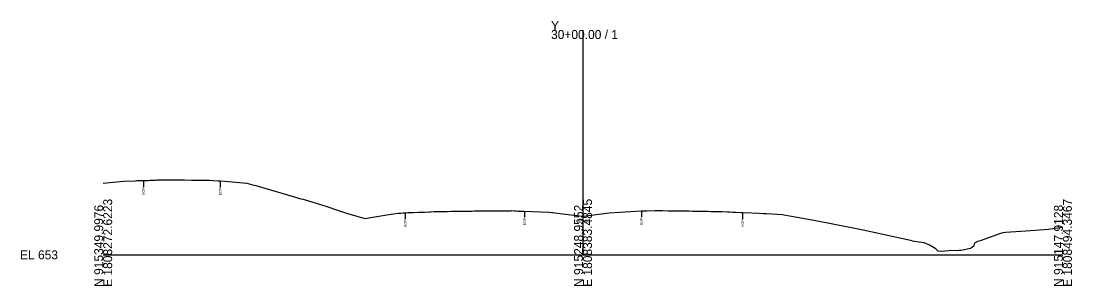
# Model space of a CAD drawing. Extents: x -26 to 3303, y -30 to 9580.
# Drawn here: x 1974.3 to 2302.8, y -9.7 to 72.9 of the extents above; entities that cross this region are included whole.
import ezdxf

# ---------------------------------------------------------------- set-up
doc = ezdxf.new("R2010")
doc.units = 0
for name, color, linetype in [('Exist Cross Section Cell', 7, 'Continuous'), ('Exist XS Center Line Elevation Label', 7, 'Continuous'), ('Exist XS Ground Line', 7, 'Continuous'), ('Old_Level_10', 7, 'Continuous')]:
    doc.layers.add(name, color=color, linetype=linetype)

msp = doc.modelspace()

# ---------------------------------------------------------------- linework, layer by layer
at = {"layer": 'Exist Cross Section Cell'}
for p, q in [((2150, 0), (2150, 70.15)), ((2000, 0), (2150, 0)), ((2150, 0), (2300, 0))]:
    msp.add_line(p, q, dxfattribs=at)
at = {"layer": 'Exist XS Ground Line'}
msp.add_lwpolyline([(2000, 22.36), (2005.33, 22.94), (2006.35, 23), (2009.84, 23.13), (2010.52, 23.16), (2011.55, 23.18), (2012.56, 23.21), (2013.38, 23.23), (2014.11, 23.25), (2014.72, 23.28), (2016.43, 23.35), (2016.86, 23.38), (2017.19, 23.38), (2017.49, 23.38), (2019.06, 23.38), (2020.95, 23.38), (2024.47, 23.37), (2025.36, 23.37), (2027.62, 23.35), (2028.24, 23.35), (2031.01, 23.33), (2031.46, 23.33), (2032.02, 23.33), (2033.16, 23.32), (2034.32, 23.2), (2035.97, 23.08), (2036.57, 23.05), (2038.02, 22.95), (2039.21, 22.86), (2044.91, 22.4), (2047.08, 21.79), (2047.69, 21.61), (2050.57, 20.77), (2059.38, 18.16), (2061.81, 17.49), (2062.49, 17.38), (2066.9, 16.03), (2068.93, 15.39), (2074.22, 13.61), (2076.01, 13.01), (2079.27, 12.1), (2081.76, 11.39), (2088.68, 12.47), (2090.75, 12.82), (2092.28, 12.97), (2092.59, 12.99), (2093.04, 13.04), (2093.77, 13.11), (2094.39, 13.16), (2095.25, 13.18), (2096.94, 13.24), (2098.71, 13.29), (2100.47, 13.34), (2102.04, 13.39), (2102.44, 13.41), (2103.49, 13.48), (2104.37, 13.53), (2104.76, 13.54), (2105.78, 13.55), (2106.16, 13.55), (2107.54, 13.57), (2108.8, 13.59), (2109.33, 13.6), (2109.89, 13.61), (2111.08, 13.62), (2112.17, 13.64), (2113.61, 13.66), (2115.29, 13.68), (2115.93, 13.69), (2117.34, 13.71), (2118.17, 13.72), (2118.95, 13.73), (2121.01, 13.75), (2122.34, 13.76), (2123.48, 13.76), (2124.7, 13.77), (2125.73, 13.77), (2127.4, 13.79), (2127.72, 13.8), (2128.6, 13.71), (2129.09, 13.69), (2129.63, 13.68), (2131.42, 13.66), (2131.73, 13.66), (2139.26, 13.3), (2140.22, 13.25), (2140.59, 13.23), (2143.62, 12.83), (2149.8, 12.03), (2150.12, 12.07), (2158.12, 13.16), (2161.38, 13.35), (2166.59, 13.67), (2168.26, 13.77), (2169.36, 13.77), (2169.67, 13.77), (2169.98, 13.78), (2172.43, 13.85), (2173.08, 13.83), (2174.79, 13.8), (2176.72, 13.79), (2179.82, 13.75), (2180.39, 13.74), (2181.86, 13.73), (2183.18, 13.7), (2184.2, 13.67), (2185.32, 13.65), (2186.58, 13.62), (2187.17, 13.61), (2187.84, 13.61), (2188.96, 13.6), (2189.99, 13.58), (2191.57, 13.55), (2192.54, 13.54), (2193.41, 13.5), (2195.11, 13.43), (2195.83, 13.42), (2196.74, 13.36), (2197.8, 13.29), (2199.46, 13.23), (2199.83, 13.22), (2202.75, 13.08), (2204.98, 12.97), (2206.36, 12.9), (2207.3, 12.86), (2212.21, 12.6), (2214.51, 12.2), (2217.58, 11.66), (2222.68, 10.75), (2226.47, 10.03), (2237.52, 7.81), (2240, 7.33), (2252.37, 4.57), (2252.91, 4.37), (2256.56, 3.85), (2258.51, 3.06), (2260.04, 2.1), (2260.91, 1.23), (2262.18, 1.12), (2264.34, 1.4), (2264.86, 1.44), (2266.99, 1.34), (2267.6, 1.43), (2268.08, 1.46), (2271.16, 2.08), (2271.77, 2.5), (2272.31, 2.91), (2272.49, 3.78), (2273.44, 4.24), (2274.21, 4.49), (2280.59, 6.77), (2281.29, 7.01), (2282.06, 7.09), (2288.37, 7.48), (2294.12, 7.9), (2295.45, 7.97), (2296.9, 8.21), (2300, 8.6)], dxfattribs=at)
at = {"layer": 'Old_Level_10'}
for p, q in [((2012.56, 23.21), (2012.56, 21.16)), ((2036.57, 23.05), (2036.57, 21)), ((2094.39, 13.16), (2094.39, 11.1)), ((2131.73, 13.66), (2131.73, 11.61)), ((2168.26, 13.77), (2168.26, 11.72)), ((2199.83, 13.22), (2199.83, 11.16))]:
    msp.add_line(p, q, dxfattribs=at)

# ---------------------------------------------------------------- texts
at = {"layer": 'Exist Cross Section Cell'}
for s, p in [('Y', (2140, 70.15)), ('30+00.00 / 1', (2140, 67.35)), ('EL 653', (1974, -1.4))]:
    msp.add_text(s, height=2.8, dxfattribs=at).set_placement(p)
for s, p in [('E 1808272.6223', (2002.8, -10)), ('E 1808383.4845', (2152.8, -10)), ('E 1808494.3467', (2302.8, -10)), ('N 915349.9976', (2000, -10)), ('N 915248.9552', (2150, -10)), ('N 915147.9128', (2300, -10))]:
    msp.add_text(s, height=2.8, rotation=90, dxfattribs=at).set_placement(p)
at = {"layer": 'Exist XS Center Line Elevation Label'}
msp.add_text('665.05', height=1, dxfattribs=at).set_placement((2147.87, 10.05))
at = {"layer": 'Old_Level_10'}
for p in [(2012.96, 18.76), (2036.96, 18.6), (2094.79, 8.71), (2132.13, 9.21), (2168.66, 9.32), (2200.23, 8.77)]:
    msp.add_text('EOP', height=0.787, rotation=90, dxfattribs=at).set_placement(p)

doc.saveas('drawing.dxf')
